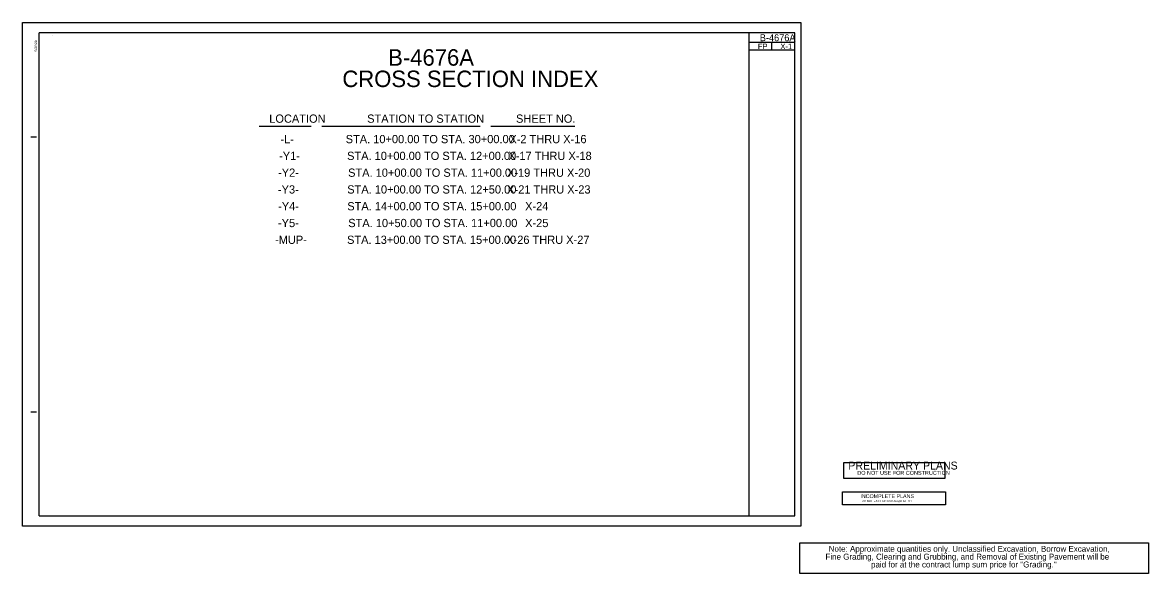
# Model space of a CAD drawing. Extents: x 1370990 to 1373449, y 877504 to 878708.
import ezdxf

# ---------------------------------------------------------------- set-up
doc = ezdxf.new("R2010")
doc.units = 0
for name, color, linetype in [('P_RDY_Grid_Mask', 7, 'Continuous'), ('Prop XSC Text', 7, 'Continuous'), ('Sheet Sticker Preliminary CELL', 7, 'Continuous'), ('Sheet_Data_Field_CELL', 7, 'Continuous'), ('Sheet_Plot_Border_Outside_CELL', 7, 'Continuous'), ('Sheet_RDY_Sticker_Preliminary_CELL', 7, 'Continuous'), ('Sheet_Sticker_Incomplete_CELL', 7, 'Continuous'), ('Sheet_Title_Block_Text', 7, 'Continuous')]:
    doc.layers.add(name, color=color, linetype=linetype)

msp = doc.modelspace()

# ---------------------------------------------------------------- linework, layer by layer
at = {"layer": 'P_RDY_Grid_Mask'}
msp.add_lwpolyline([(1372688.1, 877571.2), (1373449.1, 877571.2), (1373449.1, 877504.5), (1372688.1, 877504.5)], close=True, dxfattribs=at)
at = {"layer": 'Sheet Sticker Preliminary CELL'}
for p, q in [((1371507.2, 878481), (1371620.7, 878481)), ((1371643.9, 878481), (1371989.6, 878481)), ((1372012.9, 878481), (1372196.3, 878481))]:
    msp.add_line(p, q, dxfattribs=at)
at = {"layer": 'Sheet_Data_Field_CELL'}
msp.add_line((1370990.3, 877607.6), (1370990.3, 877607.6), dxfattribs=at)
at = {"layer": 'Sheet_Plot_Border_Outside_CELL'}
msp.add_lwpolyline([(1370990.3, 878707.6), (1372690.3, 878707.6), (1372690.3, 877607.6), (1370990.3, 877607.6)], close=True, dxfattribs=at)
at = {"layer": 'Sheet_RDY_Sticker_Preliminary_CELL'}
msp.add_lwpolyline([(1372783.8, 877711.7), (1372783.8, 877747), (1373004.3, 877747), (1373004.3, 877711.7)], close=True, dxfattribs=at)
at = {"layer": 'Sheet_Sticker_Incomplete_CELL'}
msp.add_lwpolyline([(1372781, 877682.7), (1373006, 877682.7), (1373006, 877654.1), (1372781, 877654.1)], close=True, dxfattribs=at)
at = {"layer": 'Sheet_Title_Block_Text'}
for p, q in [((1371026.8, 877630.1), (1371026.8, 878685.1)), ((1372676.8, 878685.1), (1371026.8, 878685.1)), ((1371056.8, 878680.1), (1371056.8, 878680.1)), ((1372576.8, 877630.1), (1372576.8, 878685.1)), ((1372676.8, 877630.1), (1372676.8, 878685.1)), ((1372676.8, 878663.6), (1372576.8, 878663.6)), ((1372626.8, 878647.1), (1372626.8, 878663.6)), ((1372676.8, 878647.1), (1372576.8, 878647.1)), ((1371008.3, 878457.6), (1371020.8, 878457.6)), ((1371008.3, 877857.6), (1371020.8, 877857.6)), ((1371026.8, 877630.1), (1372676.8, 877630.1)), ((1371056.8, 877630.1), (1371056.8, 877630.1))]:
    msp.add_line(p, q, dxfattribs=at)
for centre in [(1372626.7, 878674.3), (1372626.8, 878674.3), (1372601.7, 878655.4), (1372601.8, 878655.4), (1372576.8, 878647.1)]:
    msp.add_circle(centre, 0.06, dxfattribs=at)

# ---------------------------------------------------------------- texts
at = {"layer": 'Prop XSC Text'}
for s, p in [('Fine Grading, Clearing and Grubbing, and Removal of Existing Pavement will be ', (1372743.8, 877534.7)), ('Note: Approximate quantities only. Unclassified Excavation, Borrow Excavation, ', (1372750.8, 877551.8)), ('paid for at the contract lump sum price for "Grading."', (1372843.2, 877517.6))]:
    msp.add_text(s, height=13.02, dxfattribs=at).set_placement(p)
at = {"layer": 'Sheet Sticker Preliminary CELL'}
for s, height, p in [('B-4676A', 15, (1372600.3, 878666.8)), ('B-4676A', 36, (1371788.8, 878613.3)), ('FP', 12, (1372596.1, 878649.4)), ('X-1', 12, (1372645.3, 878649.4)), ('CROSS SECTION INDEX', 36, (1371688.8, 878566.6)), ('LOCATION', 18, (1371529.1, 878488.7)), ('STATION TO STATION', 18, (1371742.9, 878488.7)), ('SHEET NO.', 18, (1372068, 878488.7)), ('-L-', 18, (1371553.7, 878444)), ('STA. 10+00.00 TO STA. 30+00.00', 18, (1371696, 878444)), ('X-2 THRU X-16', 18, (1372053.4, 878444)), ('-Y1-', 18, (1371550.6, 878407.4)), ('STA. 10+00.00 TO STA. 12+00.00', 18, (1371699.1, 878407.4)), ('X-17 THRU X-18', 18, (1372051.3, 878407.4)), ('-Y2-', 18, (1371548.4, 878370.7)), ('STA. 10+00.00 TO STA. 11+00.00', 18, (1371701.3, 878370.7)), ('X-19 THRU X-20', 18, (1372048.3, 878370.7)), ('-Y3-', 18, (1371548.1, 878334.1)), ('STA. 10+00.00 TO STA. 12+50.00', 18, (1371699.4, 878334.1)), ('X-21 THRU X-23', 18, (1372048.8, 878334.1)), ('-Y4-', 18, (1371548.5, 878297.5)), ('STA. 14+00.00 TO STA. 15+00.00', 18, (1371699.5, 878297.5)), ('X-24', 18, (1372087.8, 878297.5)), ('STA. 10+50.00 TO STA. 11+00.00', 18, (1371701.6, 878260.8)), ('X-25', 18, (1372087.9, 878260.8)), ('-Y5-', 18, (1371548.2, 878260.8)), ('-MUP-', 18, (1371541.8, 878224.2)), ('STA. 13+00.00 TO STA. 15+00.00', 18, (1371699, 878224.2)), ('X-26 THRU X-27', 18, (1372046.5, 878224.2))]:
    msp.add_text(s, height=height, dxfattribs=at).set_placement(p)
at = {"layer": 'Sheet_RDY_Sticker_Preliminary_CELL'}
for s, height, p in [('PRELIMINARY PLANS', 17.28, (1372793.6, 877731.5)), ('DO NOT USE FOR CONSTRUCTION', 8.64, (1372813.2, 877719.9))]:
    msp.add_text(s, height=height, dxfattribs=at).set_placement(p)
at = {"layer": 'Sheet_Sticker_Incomplete_CELL'}
for s, height, p in [('INCOMPLETE PLANS', 8.438, (1372819.9, 877669.1)), ('DO NOT USE FOR R/W ACQUISITION', 4.556, (1372822.7, 877660.6))]:
    msp.add_text(s, height=height, dxfattribs=at).set_placement(p)
at = {"layer": 'Sheet_Title_Block_Text'}
msp.add_text('5/26/20', height=5.25, rotation=90, dxfattribs=at).set_placement((1371022.1, 878644.3))

doc.saveas('drawing.dxf')
